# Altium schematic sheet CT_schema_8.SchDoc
size 277 x 170 mm
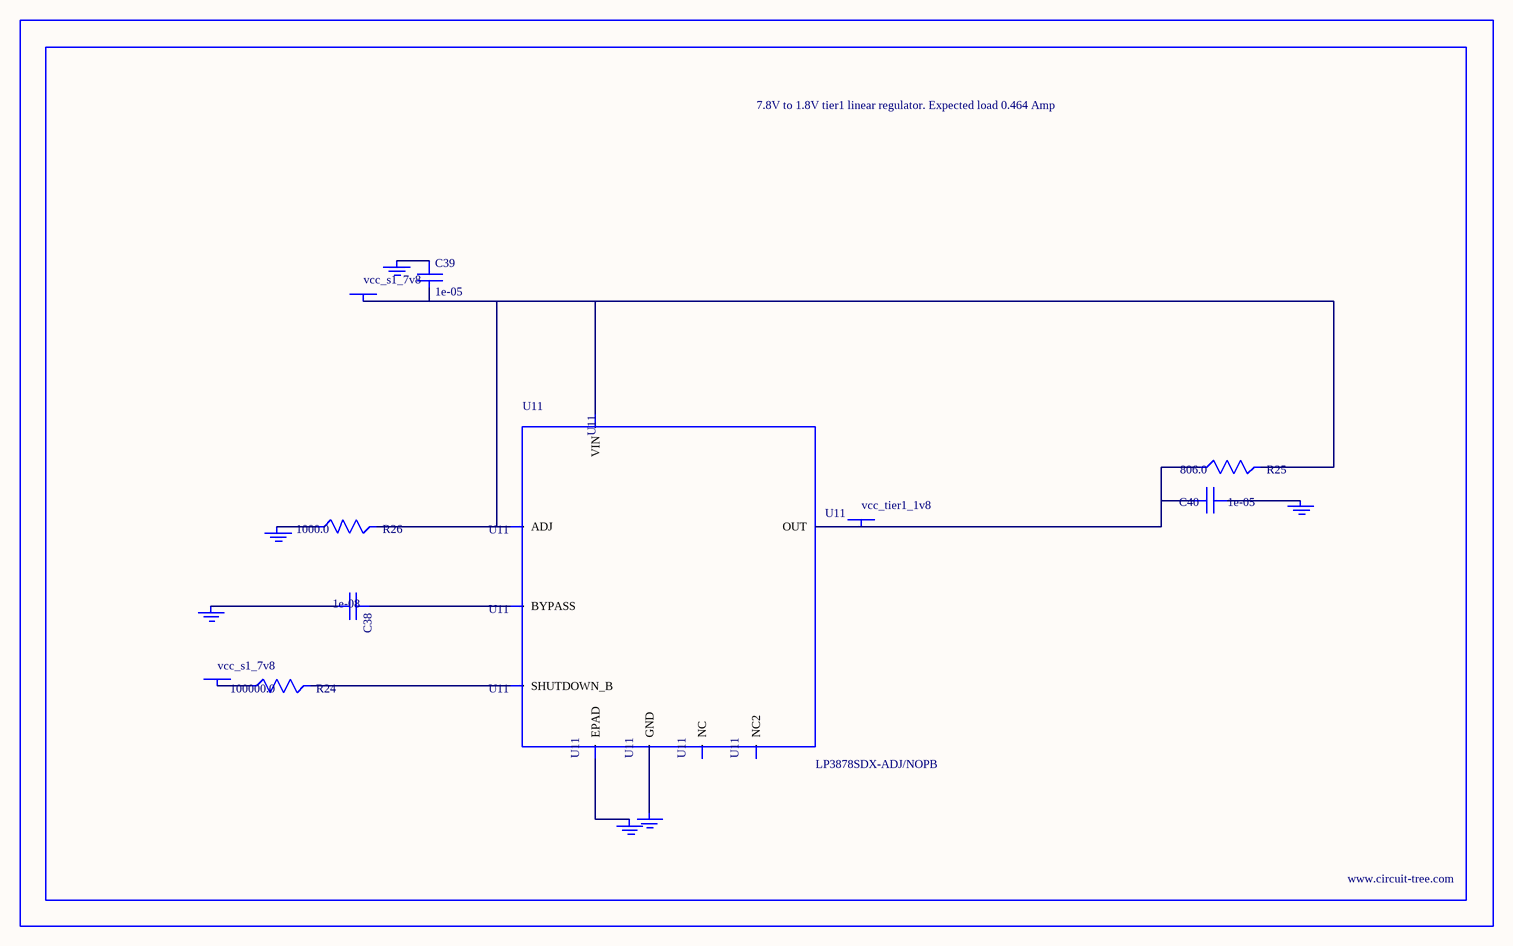
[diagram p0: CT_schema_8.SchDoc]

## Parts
BORDER7  (no value)
C38  1e-08  [C0402]
C39  1e-05  [C1206]
C40  1e-05  [C0805]
GND_INSTANCE_7_0  (no value)
GND_INSTANCE_7_1  (no value)
GND_INSTANCE_7_2  (no value)
GND_INSTANCE_7_3  (no value)
GND_INSTANCE_7_4  (no value)
GND_INSTANCE_7_5  (no value)
POWER_INSTANCE_7_0  vcc_s1_7v8
POWER_INSTANCE_7_1  vcc_s1_7v8
POWER_INSTANCE_7_2  vcc_tier1_1v8
R24  100000.0  [R0603]
R25  806.0  [R0603]
R26  1000.0  [R0603]
U11  LP3878SDX-ADJ/NOPB  [WSON-8]

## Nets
NetC38_1: C38.1 U11.1(BYPASS)
NetC38_2: C38.2 GND_INSTANCE_7_0.0(GND)
NetC39_1: C39.1 GND_INSTANCE_7_1.0(GND)
NetC39_2: C39.2 POWER_INSTANCE_7_0.0(PWR) R25.2 R26.2 U11.4(VIN) U11.6(ADJ)
NetC40_1: C40.1 GND_INSTANCE_7_2.0(GND)
NetC40_2: C40.2 POWER_INSTANCE_7_2.0(PWR) R25.1 U11.5(OUT)
NetGND_INSTANCE_7_3_0: GND_INSTANCE_7_3.0(GND) R26.1
NetGND_INSTANCE_7_4_0: GND_INSTANCE_7_4.0(GND) U11.PAD(EPAD)
NetGND_INSTANCE_7_5_0: GND_INSTANCE_7_5.0(GND) U11.3(GND)
NetPOWER_INSTANCE_7_1_0: POWER_INSTANCE_7_1.0(PWR) R24.1
NetR24_2: R24.2 U11.8(SHUTDOWN_B)

Not connected (* = marked no-connect by the designer): U11 2(NC) 7(NC2)

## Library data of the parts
BORDER7 = BORDER_PAGE7
C38 = C0402C103K3RAC
C39 = C1206C106K3RACTU
C40 = GRM219R60J106ME19D
GND_INSTANCE_7_0-GND_INSTANCE_7_5 = GND
POWER_INSTANCE_7_0-POWER_INSTANCE_7_2 = PWR
R24 = RC0603JR-07100KL
R25 = ERJ-3EKF8060V
R26 = RC0603JR-071KL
